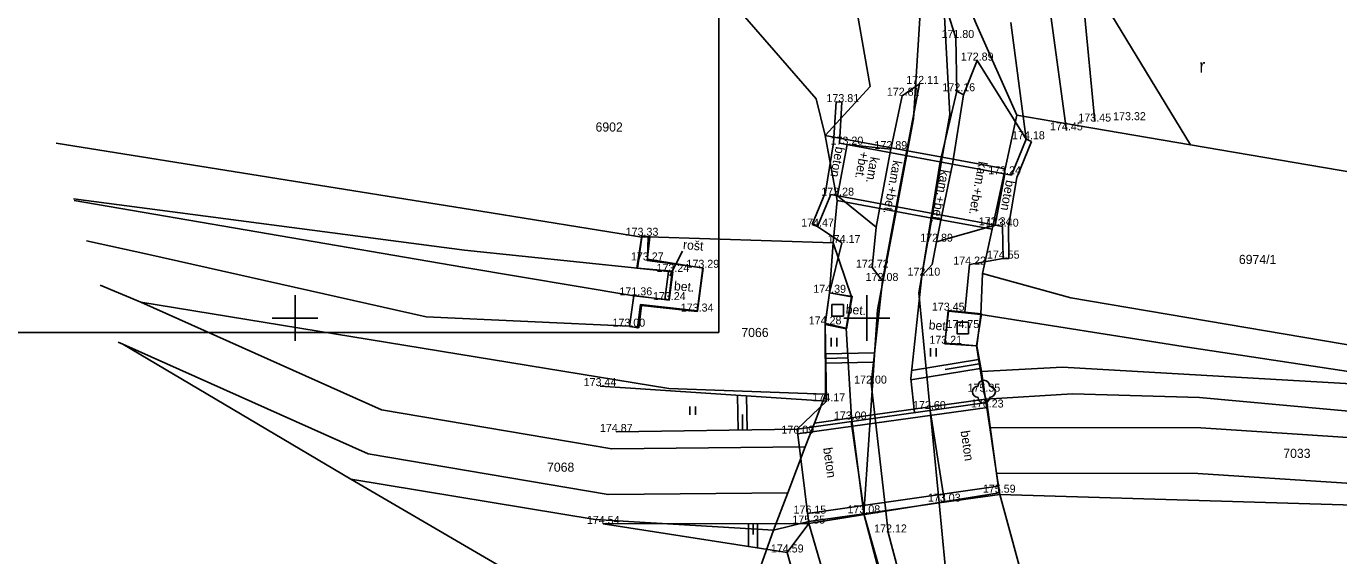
# Model space of a CAD drawing. Extents: x -612546 to -611926, y -1201932 to -1200444.
# Drawn here: x -612123.5 to -612008.7, y -1201270.8 to -1201224.5 of the extents above; entities that cross this region are included whole.
import ezdxf

# ---------------------------------------------------------------- set-up
doc = ezdxf.new("R2010")
doc.units = 0
for name, color, linetype in [('11_silnice_chodník_obr_zp_plochy', 7, 'Continuous'), ('14 hrana pata svahu', 7, 'Continuous'), ('15 šrafy', 7, 'Continuous'), ('22 stromy_keře', 7, 'Continuous'), ('26 šachta nerozlišená', 7, 'Continuous'), ('40 popisy', 7, 'Continuous'), ('61 legenda křížky', 7, 'Continuous'), ('Hranice parcel', 7, 'Continuous'), ('Parcelní čísla', 7, 'Continuous'), ('Vnitřní kresba', 7, 'Continuous'), ('Vrstva 36', 7, 'Continuous'), ('Vrstva 63', 7, 'Continuous'), ('výška bodu', 7, 'Continuous')]:
    doc.layers.add(name, color=color, linetype=linetype)

msp = doc.modelspace()

# ---------------------------------------------------------------- linework, layer by layer
at = {"layer": '11_silnice_chodník_obr_zp_plochy'}
for p, q in [((-612052.9, -1201234.67), (-612052.69, -1201231.08)), ((-612052.19, -1201231.11), (-612052.69, -1201231.08)), ((-612052.4, -1201234.7), (-612052.19, -1201231.11)), ((-612052.9, -1201234.67), (-612053.61, -1201239)), ((-612052.4, -1201234.7), (-612037.35, -1201237.5)), ((-612037.35, -1201237.5), (-612036.07, -1201234.36)), ((-612036.89, -1201237.69), (-612035.61, -1201234.55)), ((-612035.61, -1201234.55), (-612036.07, -1201234.36)), ((-612051.71, -1201234.83), (-612052.55, -1201239.3)), ((-612047.9, -1201235.22), (-612051.71, -1201234.83)), ((-612047.96, -1201235.53), (-612048.8, -1201240)), ((-612047.42, -1201240.26), (-612046.58, -1201235.78)), ((-612044.31, -1201240.84), (-612043.58, -1201236.34)), ((-612043.43, -1201241.01), (-612042.52, -1201236.54)), ((-612037.94, -1201237.39), (-612038.78, -1201241.88)), ((-612036.89, -1201237.69), (-612037.62, -1201241.99)), ((-612053.61, -1201239), (-612054.77, -1201241.81)), ((-612053.15, -1201239.19), (-612054.31, -1201242)), ((-612038.12, -1201242), (-612053.15, -1201239.19)), ((-612049.18, -1201242.05), (-612052.55, -1201239.3)), ((-612054.31, -1201242), (-612054.77, -1201241.81)), ((-612038.12, -1201242), (-612038.07, -1201244.8)), ((-612037.62, -1201241.99), (-612037.57, -1201244.79)), ((-612067.22, -1201246.3), (-612066.13, -1201244.14)), ((-612037.57, -1201244.79), (-612038.07, -1201244.8)), ((-612067.34, -1201245.92), (-612067.65, -1201248.38)), ((-612056.05, -1201260.12), (-612039.45, -1201257.82)), ((-612044.46, -1201258.07), (-612043.2, -1201266.04)), ((-612051.37, -1201259.04), (-612050.21, -1201267.18)), ((-612055.19, -1201267.1), (-612038.5, -1201264.69))]:
    msp.add_line(p, q, dxfattribs=at)
for points in [[(-612041.53, -1201230.46), (-612040.35, -1201227.48), (-612036.07, -1201234.36)], [(-612047.96, -1201235.53), (-612046.91, -1201230.55), (-612045.4, -1201229.52)], [(-612046.58, -1201235.78), (-612045.4, -1201229.52)], [(-612043.58, -1201236.34), (-612042.14, -1201230.16)], [(-612042.52, -1201236.54), (-612041.53, -1201230.46), (-612042.14, -1201230.16)], [(-612048.64, -1201246.75), (-612049.52, -1201245.59), (-612049.18, -1201242.05), (-612048.8, -1201240)], [(-612048.64, -1201246.75), (-612047.42, -1201240.26)], [(-612045.18, -1201246.29), (-612044.31, -1201240.84)], [(-612043.9, -1201243.32), (-612043.43, -1201241.01)], [(-612045.18, -1201246.29), (-612044.29, -1201245.32), (-612043.9, -1201243.32), (-612038.78, -1201241.88)]]:
    msp.add_lwpolyline(points, dxfattribs=at)
for points in [[(-612070.75, -1201250.75), (-612069.94, -1201250.85), (-612069.69, -1201248.91), (-612064.84, -1201249.43), (-612064.34, -1201245.6), (-612069.2, -1201244.96), (-612068.96, -1201242.88), (-612069.66, -1201242.8), (-612070.11, -1201245.63), (-612066.96, -1201245.96), (-612067.27, -1201248.43), (-612070.38, -1201248.01)], [(-612053.65, -1201250.55), (-612053.25, -1201247.79), (-612051.28, -1201248.1), (-612051.78, -1201250.94)], [(-612042.88, -1201249.35), (-612043.19, -1201252.25), (-612040.42, -1201252.43), (-612039.96, -1201249.63)], [(-612055.08, -1201267.97), (-612056.1, -1201259.71), (-612039.51, -1201257.37), (-612038.42, -1201265.27)]]:
    msp.add_lwpolyline(points, close=True, dxfattribs=at)
at = {"layer": '14 hrana pata svahu'}
for p, q in [((-612031.02, -1201222.77), (-612030.07, -1201232.81)), ((-612037.41, -1201224.15), (-612036.07, -1201234.36)), ((-612033.91, -1201223.55), (-612032.55, -1201233.58)), ((-612042.21, -1201225.5), (-612042.14, -1201230.16)), ((-612053.52, -1201257.28), (-612053.65, -1201250.55)), ((-612049.27, -1201258.75), (-612049.62, -1201255.73)), ((-612049.27, -1201258.75), (-612048.34, -1201266.88)), ((-612056.96, -1201270.5), (-612055.08, -1201267.97)), ((-612048.13, -1201268.75), (-612048.34, -1201266.88))]:
    msp.add_line(p, q, dxfattribs=at)
for points in [[(-612042.21, -1201225.5), (-612044.5, -1201218.38), (-612048.83, -1201210.69), (-612059.87, -1201197.37), (-612070.03, -1201185.96)], [(-612053.25, -1201247.79), (-612052.19, -1201243.43), (-612054.31, -1201242)], [(-612041.43, -1201249.47), (-612041.01, -1201245.32), (-612038.07, -1201244.8)], [(-612049.62, -1201255.73), (-612048.64, -1201246.75)], [(-612045.18, -1201246.29), (-612046.16, -1201255.27), (-612045.82, -1201258.26)], [(-612039.51, -1201257.37), (-612039.76, -1201256.44), (-612040.42, -1201252.43)], [(-612071.91, -1201259.96), (-612056.1, -1201259.71), (-612053.52, -1201257.28), (-612073.33, -1201255.95)], [(-612045.18, -1201301.85), (-612055.08, -1201267.97), (-612073.05, -1201268)], [(-612048.01, -1201302.49), (-612056.96, -1201270.5), (-612073.05, -1201268)], [(-612039.66, -1201300.7), (-612048.13, -1201268.75)]]:
    msp.add_lwpolyline(points, dxfattribs=at)
at = {"layer": '15 šrafy'}
for p, q in [((-612049.33, -1201253.05), (-612053.6, -1201253.13)), ((-612051.67, -1201253.49), (-612053.59, -1201253.53)), ((-612049.41, -1201253.85), (-612053.58, -1201253.93)), ((-612046.09, -1201254.58), (-612040.22, -1201253.62)), ((-612043.16, -1201254.51), (-612040.16, -1201254.01)), ((-612046.14, -1201255.41), (-612040.09, -1201254.41)), ((-612061.31, -1201256.76), (-612061.26, -1201259.79)), ((-612060.51, -1201256.81), (-612060.46, -1201259.78)), ((-612060.88, -1201258.42), (-612060.86, -1201259.79)), ((-612060.35, -1201269.97), (-612060.35, -1201267.98)), ((-612059.95, -1201268.92), (-612059.95, -1201267.98)), ((-612059.55, -1201270.1), (-612059.55, -1201267.98))]:
    msp.add_line(p, q, dxfattribs=at)
at = {"layer": '22 stromy_keře'}
msp.add_circle((-612039.76, -1201256.44), 0.05, dxfattribs=at)
for centre, start, end in [((-612040.26, -1201256.44), 90, 270), ((-612039.76, -1201255.94), 0, 180), ((-612039.26, -1201256.44), 270, 90), ((-612039.76, -1201256.94), 180, 0)]:
    msp.add_arc(centre, 0.5, start, end, dxfattribs=at)
at = {"layer": '26 šachta nerozlišená'}
for points in [[(-612052.05, -1201249.82), (-612052.05, -1201248.82), (-612053.05, -1201248.82), (-612053.05, -1201249.82)], [(-612041.1, -1201251.37), (-612041.1, -1201250.37), (-612042.1, -1201250.37), (-612042.1, -1201251.37)]]:
    msp.add_lwpolyline(points, close=True, dxfattribs=at)
at = {"layer": '61 legenda křížky'}
for p, q in [((-612100, -1201252), (-612100, -1201248)), ((-612050, -1201252), (-612050, -1201248)), ((-612102, -1201250), (-612098, -1201250)), ((-612052, -1201250), (-612048, -1201250))]:
    msp.add_line(p, q, dxfattribs=at)
at = {"layer": 'Hranice parcel'}
msp.add_line((-612021.69, -1201234.86), (-611955.36, -1201246.17), dxfattribs=at)
for points in [[(-612492.54, -1200475.45), (-612489.15, -1200479.9), (-612487.29, -1200482.34), (-612470.55, -1200499.86), (-612454.58, -1200517.89), (-612449.12, -1200526.98), (-612444.88, -1200537.01), (-612400.71, -1200658.68), (-612382.76, -1200708.97), (-612320.94, -1200880.21), (-612316.28, -1200891.06), (-612307.37, -1200903.62), (-612259.67, -1200958.71), (-612214.29, -1201012.03), (-612172.62, -1201060.98), (-612120.7, -1201123.05), (-612073.85, -1201178.4), (-612068.4, -1201184.83), (-612055.42, -1201199.11), (-612044.78, -1201213.9), (-612040.42, -1201224.33), (-612036.87, -1201232.26)], [(-612053.63, -1201234.04), (-612049.72, -1201229.74), (-612051.31, -1201220.57), (-612058.28, -1201208.42), (-612073.89, -1201189.58), (-612079.31, -1201183.16), (-612173.25, -1201072.99), (-612266.53, -1200963.98), (-612308.11, -1200916.05), (-612320.05, -1200901.46), (-612326.37, -1200888.91), (-612352.76, -1200817.26), (-612383.45, -1200732.24), (-612424.46, -1200618.96), (-612450.75, -1200547.77), (-612455.75, -1200534.91), (-612462.05, -1200524.68), (-612490.01, -1200492.58), (-612497.19, -1200482.99)], [(-612030.14, -1201209.55), (-612029.49, -1201222.03), (-612021.69, -1201234.86)], [(-612053.63, -1201234.04), (-612054.43, -1201230.81), (-612058.14, -1201226.56), (-612061.86, -1201222.29)], [(-612036.87, -1201232.26), (-612037.9, -1201236.96), (-612039.05, -1201242.23), (-612039.89, -1201246.1)], [(-612021.69, -1201234.86), (-612032.8, -1201232.96), (-612036.87, -1201232.26)], [(-612120.88, -1201234.69), (-612083.74, -1201240.64), (-612069.66, -1201242.91), (-612069.11, -1201242.88), (-612052.95, -1201243.41)], [(-612052.95, -1201243.41), (-612052.59, -1201239.73), (-612053.63, -1201234.04)], [(-612053.61, -1201256.64), (-612053.64, -1201250.48), (-612053.25, -1201247.8), (-612052.95, -1201243.41)], [(-612027.1, -1201355.18), (-612050.25, -1201267.11), (-612051.33, -1201258.72), (-612051.81, -1201250.87), (-612051.34, -1201248.14), (-612052.95, -1201243.41)], [(-612039.89, -1201246.1), (-612040.03, -1201249.7), (-612040.39, -1201252.42), (-612039.97, -1201254.67), (-612039.62, -1201257.09)], [(-611954.97, -1201261.74), (-611964.06, -1201259.77), (-612032.15, -1201248.22), (-612039.89, -1201246.1)], [(-612117.03, -1201247.11), (-612113.47, -1201248.61), (-612067.3, -1201256.16), (-612053.61, -1201256.64)], [(-612115.48, -1201252.1), (-612115.07, -1201252.28), (-612095.11, -1201264.08), (-612077.83, -1201274.18), (-612063.31, -1201283.15)], [(-612060.22, -1201274.37), (-612058.16, -1201268.54), (-612056.92, -1201265.29), (-612055.38, -1201261.27), (-612054.58, -1201259.18), (-612053.61, -1201256.64)], [(-611954.86, -1201266.33), (-611964.99, -1201265.2), (-611994.82, -1201259.34), (-612020.92, -1201256.96), (-612032.02, -1201256.62), (-612039.62, -1201257.09)], [(-612039.62, -1201257.09), (-612039.25, -1201259.57), (-612038.66, -1201263.56), (-612038.38, -1201265.42)], [(-612038.38, -1201265.42), (-611995.74, -1201266.7), (-611983.63, -1201266.82)], [(-612038.38, -1201265.42), (-612018.73, -1201337.57), (-612009.76, -1201369.19)]]:
    msp.add_lwpolyline(points, dxfattribs=at)
at = {"layer": 'Vnitřní kresba'}
for p, q in [((-612053.63, -1201234.04), (-612046.44, -1201235.38)), ((-612046.44, -1201235.38), (-612047.44, -1201240.68)), ((-612046.44, -1201235.38), (-612043.4, -1201235.94)), ((-612043.4, -1201235.94), (-612044.32, -1201241.26)), ((-612043.4, -1201235.94), (-612037.9, -1201236.96)), ((-612052.59, -1201239.73), (-612047.44, -1201240.68)), ((-612047.44, -1201240.68), (-612044.32, -1201241.26)), ((-612044.32, -1201241.26), (-612039.05, -1201242.23)), ((-612069.66, -1201242.91), (-612070.04, -1201245.64)), ((-612070.38, -1201248.04), (-612070.75, -1201250.71)), ((-612053.25, -1201247.8), (-612051.34, -1201248.14)), ((-612053.64, -1201250.48), (-612051.81, -1201250.87)), ((-612039.62, -1201257.09), (-612044.49, -1201257.77)), ((-612054.58, -1201259.18), (-612051.33, -1201258.72)), ((-612051.33, -1201258.72), (-612049.67, -1201258.49)), ((-612049.67, -1201258.49), (-612050.25, -1201267.11)), ((-612044.49, -1201257.77), (-612049.67, -1201258.49)), ((-612044.49, -1201257.77), (-612043.67, -1201266.17)), ((-612038.38, -1201265.42), (-612043.67, -1201266.17)), ((-612043.67, -1201266.17), (-612050.25, -1201267.11)), ((-612055.06, -1201267.79), (-612058.16, -1201268.54)), ((-612050.25, -1201267.11), (-612055.06, -1201267.79))]:
    msp.add_line(p, q, dxfattribs=at)
for points in [[(-612043.4, -1201235.94), (-612042.74, -1201232.18), (-612043.25, -1201222.56), (-612046.39, -1201214.77), (-612058.41, -1201199.4), (-612069.48, -1201185.76)], [(-612046.44, -1201235.38), (-612045.91, -1201232.58), (-612045.36, -1201223.81), (-612054.03, -1201209.46), (-612069.5, -1201191.14), (-612072.26, -1201188.17)], [(-612119.37, -1201239.58), (-612085.18, -1201244.05), (-612070.04, -1201245.64)], [(-612070.38, -1201248.04), (-612085.34, -1201245.55), (-612119.32, -1201239.72)], [(-612049.67, -1201258.49), (-612049.06, -1201249.29), (-612047.44, -1201240.68)], [(-612044.49, -1201257.77), (-612045.46, -1201247.78), (-612044.32, -1201241.26)], [(-612070.75, -1201250.71), (-612088.52, -1201249.89), (-612112.79, -1201244.44), (-612118.23, -1201243.25)], [(-612069.11, -1201242.88), (-612069.19, -1201244.85), (-612064.3, -1201245.64), (-612064.8, -1201249.38), (-612069.78, -1201248.81), (-612070.06, -1201250.86), (-612070.75, -1201250.71)], [(-612070.38, -1201248.04), (-612067.32, -1201248.4), (-612067.03, -1201245.91), (-612070.04, -1201245.64)], [(-612055.38, -1201261.27), (-612072.31, -1201261.44), (-612092.43, -1201258.02), (-612113.47, -1201248.61)], [(-612040.39, -1201252.42), (-612043.19, -1201252.2), (-612042.86, -1201249.39), (-612040.03, -1201249.7)], [(-612040.03, -1201249.7), (-612022.34, -1201252.49), (-611996.5, -1201256.4), (-612032.89, -1201254.3), (-612039.97, -1201254.67)], [(-612056.92, -1201265.29), (-612072.63, -1201265.44), (-612093.6, -1201261.88), (-612115.07, -1201252.28)], [(-612039.25, -1201259.57), (-612020.79, -1201259.6), (-611995.5, -1201261.25), (-611964.99, -1201265.2)], [(-612058.16, -1201268.54), (-612073.74, -1201267.63), (-612095.11, -1201264.08)], [(-612038.66, -1201263.56), (-612021.05, -1201263.59), (-611995.94, -1201265.23), (-611983.63, -1201266.82)], [(-612167.45, -1201850.95), (-612159.31, -1201839.87), (-612135.2, -1201807.83), (-612099.97, -1201758.55), (-612082.71, -1201730.21), (-612068.43, -1201702.85), (-612066.16, -1201687.46), (-612066.16, -1201656.85), (-612064.63, -1201639.3), (-612057.32, -1201615.06), (-612036.83, -1201583.77), (-612007.13, -1201540.95), (-611995.21, -1201517.05), (-611990.85, -1201487.68), (-611992.18, -1201466.53), (-612005.11, -1201415.22), (-612025.88, -1201339.7), (-612042.61, -1201277.13), (-612043.67, -1201266.17)], [(-612170.38, -1201848.81), (-612152.03, -1201823.55), (-612114.84, -1201773.75), (-612096.57, -1201746.92), (-612078.95, -1201716.04), (-612070.37, -1201697.01), (-612068.25, -1201638.15), (-612062.56, -1201619.7), (-612053.03, -1201601.55), (-612018.56, -1201552.89), (-611999.85, -1201519.56), (-611995.35, -1201499.82), (-611993.63, -1201480.57), (-612000.19, -1201450.02), (-612024.45, -1201357.81), (-612050.25, -1201267.11)]]:
    msp.add_lwpolyline(points, dxfattribs=at)
at = {"layer": 'Vrstva 36'}
for p, q in [((-612053.11, -1201252.48), (-612053.11, -1201251.73)), ((-612052.61, -1201252.48), (-612052.61, -1201251.73)), ((-612044.44, -1201253.37), (-612044.44, -1201252.62)), ((-612043.94, -1201253.37), (-612043.94, -1201252.62)), ((-612065.48, -1201258.47), (-612065.48, -1201257.72)), ((-612064.98, -1201258.47), (-612064.98, -1201257.72))]:
    msp.add_line(p, q, dxfattribs=at)
at = {"layer": 'Vrstva 63'}
for p, q in [((-612062.93, -1200831.26), (-612062.93, -1201251.26)), ((-612062.93, -1201251.26), (-612359.93, -1201251.26))]:
    msp.add_line(p, q, dxfattribs=at)

# ---------------------------------------------------------------- texts
at = {"layer": '40 popisy'}
for s, rotation, p in [('beton', 259.5813, (-612052.71, -1201234.96)), ('+bet.', 259.6589, (-612050.6, -1201235.38)), (' kam.', 259.6589, (-612049.62, -1201235.56)), ('kam.+bet.', 259.6589, (-612047.7, -1201236.16)), ('kam.+bet.', 259.6589, (-612040.22, -1201236.25)), ('kam.+bet.', 259.6589, (-612043.51, -1201236.97)), ('beton', 259.5813, (-612037.82, -1201237.89)), ('rošt', 355.2133, (-612066.1, -1201243.96)), ('bet.', 355.2133, (-612066.89, -1201247.56)), ('bet.', 355.2133, (-612051.87, -1201249.6)), ('bet.', 355.2133, (-612044.61, -1201250.98)), ('beton', 278.0861, (-612041.8, -1201259.89)), ('beton', 278.0861, (-612053.82, -1201261.37))]:
    msp.add_text(s, height=0.8, rotation=rotation, dxfattribs=at).set_placement(p)
at = {"layer": 'Parcelní čísla'}
for s, p in [('6902', (-612073.72, -1201233.69)), ('6974/1', (-612017.46, -1201245.27)), ('7066', (-612060.97, -1201251.66)), ('7033', (-612013.58, -1201262.23)), ('7068', (-612077.96, -1201263.44))]:
    msp.add_text(s, height=0.8, dxfattribs=at).set_placement(p)
at = {"layer": 'Vrstva 36'}
msp.add_text('r', height=1.2, dxfattribs=at).set_placement((-612020.93, -1201228.54))
at = {"layer": 'výška bodu'}
for s, p in [('171.80', (-612043.47, -1201225.5)), ('172.89', (-612041.78, -1201227.48)), ('172.11', (-612046.55, -1201229.52)), ('172.81', (-612048.25, -1201230.55)), ('172.16', (-612043.39, -1201230.16)), ('173.81', (-612053.53, -1201231.11)), ('173.45', (-612031.5, -1201232.81)), ('173.32', (-612028.46, -1201232.69)), ('174.45', (-612033.98, -1201233.58)), ('173.20', (-612053.17, -1201234.83)), ('172.89', (-612049.33, -1201235.22)), ('174.18', (-612037.3, -1201234.36)), ('173.24', (-612039.38, -1201237.42)), ('173.28', (-612053.98, -1201239.29)), ('174.47', (-612055.74, -1201242)), ('173.34', (-612040.21, -1201241.88)), ('173.40', (-612039.58, -1201242)), ('173.33', (-612071.09, -1201242.8)), ('174.17', (-612053.42, -1201243.43)), ('172.89', (-612045.33, -1201243.32)), ('173.27', (-612070.63, -1201244.96)), ('173.29', (-612065.77, -1201245.6)), ('172.72', (-612050.95, -1201245.59)), ('174.22', (-612042.44, -1201245.32)), ('174.55', (-612039.5, -1201244.8)), ('173.24', (-612068.39, -1201245.96)), ('172.08', (-612050.1, -1201246.75)), ('172.10', (-612046.44, -1201246.29)), ('171.36', (-612071.63, -1201248.01)), ('174.39', (-612054.68, -1201247.79)), ('173.24', (-612068.7, -1201248.43)), ('173.34', (-612066.27, -1201249.43)), ('173.45', (-612044.31, -1201249.35)), ('173.00', (-612072.24, -1201250.75)), ('174.28', (-612055.08, -1201250.55)), ('174.75', (-612043.03, -1201250.87)), ('173.21', (-612044.53, -1201252.25)), ('173.44', (-612074.76, -1201255.95)), ('172.00', (-612051.11, -1201255.73)), ('175.35', (-612041.19, -1201256.44)), ('174.17', (-612054.75, -1201257.28)), ('172.60', (-612045.96, -1201257.95)), ('176.23', (-612040.9, -1201257.82)), ('173.00', (-612052.88, -1201258.87)), ('174.87', (-612073.34, -1201259.96)), ('176.09', (-612057.47, -1201260.11)), ('175.59', (-612039.85, -1201265.27)), ('173.03', (-612044.66, -1201266.05)), ('176.15', (-612056.41, -1201267.1)), ('173.08', (-612051.69, -1201267.07)), ('174.54', (-612074.48, -1201268)), ('175.35', (-612056.51, -1201267.97)), ('172.12', (-612049.36, -1201268.75)), ('174.59', (-612058.39, -1201270.5))]:
    msp.add_text(s, height=0.7, dxfattribs=at).set_placement(p)

doc.saveas('drawing.dxf')
